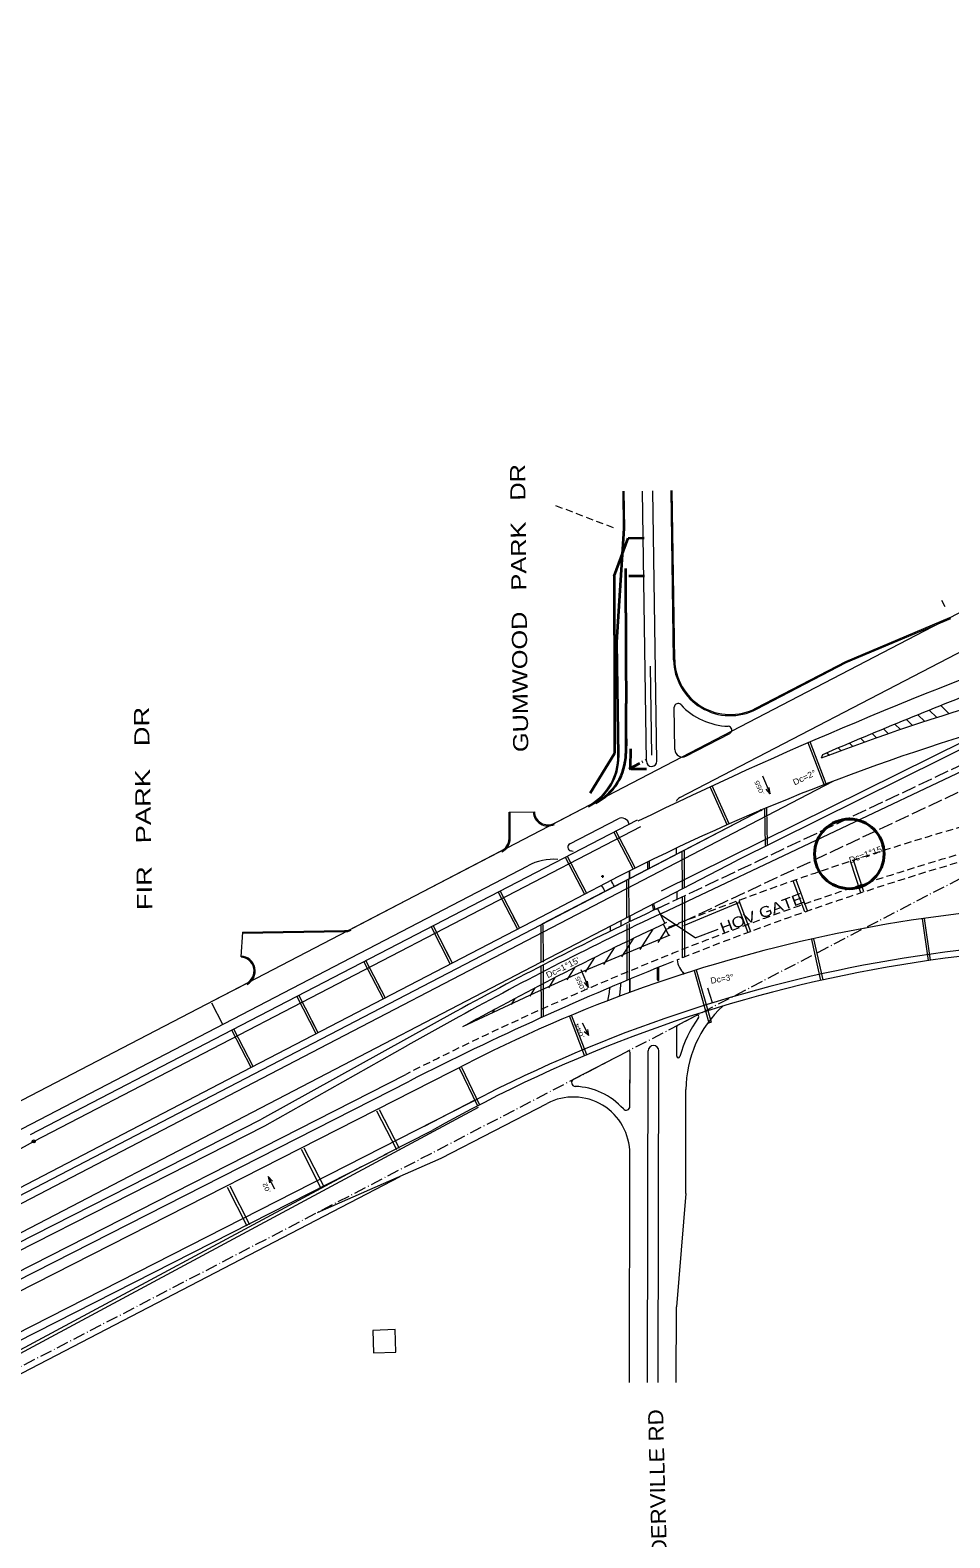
# Model space of a CAD drawing. Extents: x 2354993 to 2372084, y 6966390 to 6990057.
# Drawn here: x 2360871 to 2362087, y 6976825 to 6978818 of the extents above; entities that cross this region are included whole.
import ezdxf
from ezdxf.enums import TextEntityAlignment as Align

# ---------------------------------------------------------------- set-up
doc = ezdxf.new("R2010")
doc.units = 0
doc.header["$LTSCALE"] = 3.2
doc.header["$PDMODE"] = 32
doc.header["$PDSIZE"] = 1.6
for name, pattern in [('DASH_DOUBLE_DOT', [9.2, 5, -1.2, 0.3, -1.2, 0.3, -1.2]), ('DOT_DASHED', [7.7, 5, -1.2, 0.3, -1.2]), ('LONG_DASHED', [7.5, 6, -1.5]), ('MEDIUM_DASHED', [4.5, 3, -1.5])]:
    doc.linetypes.add(name, pattern=pattern)
for name, color, linetype, lineweight in [('1', 7, 'Continuous', 35), ('10', 7, 'Continuous', 13), ('12', 7, 'Continuous', 13), ('13', 7, 'Continuous', 13), ('17', 7, 'Continuous', 13), ('19', 7, 'Continuous', 13), ('22', 7, 'Continuous', 13), ('25', 7, 'Continuous', 13), ('5', 7, 'Continuous', 13), ('6', 7, 'Continuous', 13), ('61', 7, 'Continuous', 13), ('7', 7, 'Continuous', 13), ('8', 7, 'Continuous', 13), ('9', 7, 'Continuous', 13)]:
    doc.layers.add(name, color=color, linetype=linetype, lineweight=lineweight)

msp = doc.modelspace()

# ---------------------------------------------------------------- linework, layer by layer
at = {"layer": '1'}
for p, q in [((2361643.334, 6978096.717), (2361662.094, 6978146.92)), ((2361662.094, 6978146.92), (2361682.893, 6978147.141)), ((2361658.286, 6978106.789), (2361658.569, 6978048.231)), ((2361643.334, 6978096.717), (2361643.569, 6978048.134)), ((2361662.773, 6978096.924), (2361683.427, 6978097.144)), ((2361643.602, 6978048.134), (2361643.989, 6977988.125)), ((2361658.602, 6978048.231), (2361658.989, 6977988.222)), ((2361643.989, 6977988.22), (2361644.052, 6977928.221)), ((2361658.989, 6977988.236), (2361659.052, 6977928.237)), ((2361643.989, 6977928.245), (2361644.009, 6977868.225)), ((2361658.989, 6977928.25), (2361659.009, 6977868.23)), ((2361659.145, 6977881.526), (2361658.901, 6977862.087)), ((2361643.902, 6977862.276), (2361611.578, 6977809.791)), ((2361643.98, 6977868.474), (2361643.902, 6977862.276)), ((2361664.979, 6977868.21), (2361664.662, 6977843.018)), ((2361665.488, 6977841.938), (2361686.142, 6977842.158))]:
    msp.add_line(p, q, dxfattribs=at)
at = {"layer": '1', "lineweight": 40}
msp.add_circle((2361954.426, 6977729.502), 45.991, dxfattribs=at)
at = {"layer": '1'}
msp.add_arc((2361583.907, 6977863.029), 75, 297.46366, 359.28033, dxfattribs=at)
at = {"layer": '10', "linetype": 'DASH_DOUBLE_DOT'}
msp.add_line((2362076.387, 6978064.824), (2362080.803, 6978056.327), dxfattribs=at)
at = {"layer": '10'}
for radius, start, end in [(130, 346.40197, 354.21534), (144, 350.13301, 357.22429)]:
    msp.add_arc((2361508.6, 6977566.022), radius, start, end, dxfattribs=at)
at = {"layer": '12'}
for p, q in [((2361921.078, 6977821.033), (2361899.822, 6977876.283)), ((2361923.878, 6977822.11), (2361902.576, 6977877.48)), ((2361792.739, 6977767.876), (2361770.482, 6977818.12)), ((2361795.484, 6977769.089), (2361773.205, 6977819.384)), ((2361842.059, 6977789.602), (2361842.938, 6977740.473)), ((2361845.031, 6977791.148), (2361845.91, 6977742.017)), ((2361642.915, 6977758.312), (2361668.388, 6977709.168)), ((2361645.58, 6977759.692), (2361671.071, 6977710.513)), ((2361578.716, 6977725.035), (2361604.091, 6977676.078)), ((2361581.379, 6977726.414), (2361606.754, 6977677.459)), ((2361733.026, 6977732.938), (2361733.194, 6977683.439)), ((2361736.019, 6977734.494), (2361736.188, 6977684.995)), ((2361492.591, 6977680.393), (2361518.016, 6977631.341)), ((2361659.537, 6977694.747), (2361659.706, 6977645.247)), ((2361662.531, 6977696.303), (2361662.7, 6977646.803)), ((2361489.928, 6977679.012), (2361515.353, 6977629.96)), ((2361733.232, 6977672.053), (2361733.508, 6977592.186)), ((2361736.227, 6977673.502), (2361736.503, 6977593.373)), ((2361401.146, 6977632.993), (2361426.57, 6977583.943)), ((2361403.809, 6977634.373), (2361429.233, 6977585.323)), ((2361546.229, 6977635.86), (2361546.398, 6977586.361)), ((2361549.229, 6977635.871), (2361549.398, 6977586.371)), ((2361660.108, 6977636.189), (2361660.359, 6977562.375)), ((2361663.102, 6977637.542), (2361663.354, 6977563.627)), ((2361904.379, 6977616.377), (2361916.495, 6977562.288)), ((2361907.22, 6977617.417), (2361919.423, 6977562.942)), ((2361312.364, 6977586.974), (2361337.788, 6977537.924)), ((2361315.027, 6977588.355), (2361340.451, 6977539.305)), ((2361546.412, 6977581.859), (2361546.646, 6977512.847)), ((2361549.412, 6977581.869), (2361549.642, 6977514.202)), ((2361749.245, 6977575.374), (2361768.678, 6977506.355)), ((2361752.054, 6977576.473), (2361771.567, 6977507.169)), ((2361223.582, 6977540.955), (2361249.006, 6977491.906)), ((2361226.245, 6977542.335), (2361251.669, 6977493.286)), ((2361604.345, 6977462.835), (2361584.278, 6977515.485)), ((2361607.115, 6977463.992), (2361587.081, 6977516.552)), ((2361768.678, 6977506.355), (2361771.567, 6977507.169)), ((2361163.464, 6977447.08), (2361137.789, 6977496.485)), ((2361166.127, 6977448.464), (2361140.453, 6977497.866)), ((2361438.43, 6977446.553), (2361462.638, 6977396.418)), ((2361441.294, 6977447.521), (2361465.302, 6977397.803)), ((2361329.187, 6977390.013), (2361355.357, 6977338.869)), ((2361332.748, 6977391.835), (2361358.918, 6977340.691)), ((2361229.481, 6977338.997), (2361255.651, 6977287.852)), ((2361233.042, 6977340.819), (2361259.212, 6977289.674)), ((2361131.556, 6977288.891), (2361157.725, 6977237.746)), ((2361135.117, 6977290.713), (2361161.286, 6977239.568))]:
    msp.add_line(p, q, dxfattribs=at)
at = {"layer": '17'}
for p, q in [((2361706.685, 6977651.285), (2362482.125, 6978018.666)), ((2361735.503, 6977634.987), (2361809.727, 6977665.63)), ((2361715.491, 6977621.611), (2361708.436, 6977636.64)), ((2361438.016, 6977514.121), (2361370.31, 6977476.721)), ((2361610.08, 6977489.34), (2361601.377, 6977505.949)), ((2361610.08, 6977489.34), (2361603.892, 6977494.523)), ((2361610.08, 6977489.34), (2361608.619, 6977497.493)), ((2361185.879, 6977302.985), (2361191.568, 6977296.929))]:
    msp.add_line(p, q, dxfattribs=at)
msp.add_lwpolyline([(2361194.486, 6977286.327), (2361185.879, 6977302.985), (2361187.525, 6977294.842)], dxfattribs=at)
for radius in [4621.662, 4607.662]:
    msp.add_arc((2363672.711, 6973468.642), radius, 115.17558, 118.91596, dxfattribs=at)
at = {"layer": '19'}
for p, q in [((2361849.61, 6977808.832), (2361844.368, 6977815.28)), ((2361609.312, 6977552.985), (2361604.09, 6977559.45))]:
    msp.add_line(p, q, dxfattribs=at)
for points in [[(2361839.453, 6977832.529), (2361849.61, 6977808.832), (2361848.554, 6977817.07)], [(2361599.231, 6977576.714), (2361609.312, 6977552.985), (2361608.283, 6977561.227)]]:
    msp.add_lwpolyline(points, dxfattribs=at)
at = {"layer": '22'}
for p, q in [((2361598.925, 6977692.548), (2361605.381, 6977680.125)), ((2361513.42, 6977640.222), (2361510.193, 6977646.433)), ((2361424.688, 6977594.107), (2361421.46, 6977600.319)), ((2361335.956, 6977547.993), (2361332.727, 6977554.205)), ((2361247.222, 6977501.879), (2361243.995, 6977508.091))]:
    msp.add_line(p, q, dxfattribs=at)
at = {"layer": '25'}
for p, q in [((2358006.591, 6975920.846), (2363488.891, 6978770.331)), ((2361627.907, 6977701.471), (2361627.907, 6977697.971)), ((2361627.907, 6977701.471), (2361627.907, 6977697.971)), ((2361629.657, 6977699.721), (2361626.157, 6977699.721)), ((2361629.657, 6977699.721), (2361626.157, 6977699.721)), ((2361700.849, 6977657.382), (2361710.205, 6977637.472)), ((2361750.672, 6977618.382), (2361704.885, 6977648.793)), ((2361750.672, 6977618.382), (2361781.152, 6977630.088))]:
    msp.add_line(p, q, dxfattribs=at)
at = {"layer": '25', "linetype": 'LONG_DASHED'}
for p, q in [((2361699.088, 6977656.554), (2362455.357, 6978014.169)), ((2361711.836, 6977629.398), (2362366.21, 6977936.92))]:
    msp.add_line(p, q, dxfattribs=at)
at = {"layer": '5'}
for p, q in [((2361655.914, 6978159.454), (2361655.183, 6978208.814)), ((2361657.414, 6978159.476), (2361656.683, 6978208.836)), ((2361685.969, 6977851.923), (2361680.68, 6978209.191)), ((2361699.965, 6977852.247), (2361694.678, 6978209.398)), ((2361721.987, 6977986.095), (2361718.675, 6978209.753)), ((2361723.487, 6977986.117), (2361720.175, 6978209.775)), ((2361646.14, 6978009.412), (2361655.917, 6978159.573)), ((2361647.637, 6978009.315), (2361657.414, 6978159.476)), ((2361730.202, 6977803.996), (2362197.968, 6978047.082)), ((2361949.566, 6977983.686), (2362087.37, 6978041.875)), ((2361950.212, 6977982.331), (2362088.839, 6978040.867)), ((2361648.357, 6977859.309), (2361646.137, 6978009.293)), ((2361649.857, 6977859.331), (2361647.637, 6978009.315)), ((2361830.878, 6977921.989), (2361949.571, 6977983.689)), ((2361831.57, 6977920.658), (2361950.212, 6977982.331)), ((2361723.744, 6977867.403), (2361722.915, 6977923.363)), ((2362075.371, 6977925.53), (2362086.393, 6977914.717)), ((2362183.72, 6977908.026), (2361804.561, 6977720.528)), ((2362014.707, 6977900.992), (2362022.075, 6977893.764)), ((2362029.819, 6977907.181), (2362038.036, 6977899.119)), ((2362044.966, 6977913.333), (2362054.075, 6977904.397)), ((2362060.151, 6977919.449), (2362070.194, 6977909.597)), ((2361738.355, 6977858.679), (2361796.334, 6977888.817)), ((2361969.589, 6977882.216), (2361974.661, 6977877.24)), ((2361984.593, 6977888.51), (2361990.389, 6977882.824)), ((2361999.631, 6977894.769), (2362006.193, 6977888.331)), ((2361918.804, 6977860.536), (2361917.281, 6977856.148)), ((2361924.792, 6977863.122), (2361928.107, 6977859.87)), ((2361939.689, 6977869.522), (2361943.433, 6977865.849)), ((2361954.621, 6977875.887), (2361959.009, 6977871.582)), ((2360066.537, 6976855.596), (2361933.038, 6977825.615)), ((2361504.368, 6977784.529), (2361537.902, 6977785.151)), ((2361504.5, 6977749.834), (2361504.368, 6977784.529)), ((2361506, 6977749.84), (2361505.868, 6977784.535)), ((2361548.215, 6977636.892), (2361839.634, 6977788.342)), ((2361561.261, 6977768.424), (2361612.073, 6977794.834)), ((2361678.27, 6977765.374), (2360875.69, 6977349.365)), ((2361673.771, 6977774.306), (2361137.789, 6977496.485)), ((2361584.83, 6977742.809), (2361648.61, 6977775.962)), ((2361296.77, 6977630.952), (2361494.068, 6977733.5)), ((2361546.398, 6977586.361), (2361804.561, 6977720.528)), ((2361725.789, 6977729.178), (2361725.672, 6977737.124)), ((2360684.022, 6977274.551), (2361529.165, 6977713.873)), ((2361663.702, 6977696.911), (2361663.676, 6977706.798)), ((2361664.258, 6977697.2), (2361664.112, 6977707.018)), ((2361688.076, 6977709.578), (2361687.938, 6977718.887)), ((2361690.062, 6977710.61), (2361689.924, 6977719.864)), ((2361632.519, 6977690.849), (2361546.195, 6977645.987)), ((2361693.524, 6977662.822), (2361695.477, 6977654.856)), ((2361695.297, 6977663.744), (2361697.27, 6977655.699)), ((2361726.672, 6977669.519), (2361726.517, 6977679.969)), ((2361652.731, 6977634.39), (2361652.745, 6977641.63)), ((2361663.857, 6977639.767), (2361663.837, 6977647.394)), ((2361664.743, 6977640.193), (2361664.757, 6977647.873)), ((2361151.723, 6977626.165), (2361149.672, 6977593.441)), ((2361151.723, 6977626.165), (2361286.666, 6977628.28)), ((2361151.746, 6977624.665), (2361286.69, 6977626.78)), ((2361638.718, 6977627.566), (2361638.731, 6977634.346)), ((2361677.647, 6977602.994), (2361694.913, 6977630.236)), ((2361701.411, 6977612.468), (2361711.966, 6977629.121)), ((2361629.721, 6977583.418), (2361643.732, 6977605.524)), ((2361653.751, 6977593.312), (2361669.411, 6977618.02)), ((2358077.838, 6975783.754), (2361546.398, 6977586.361)), ((2361605.553, 6977573.308), (2361617.869, 6977592.739)), ((2361556.793, 6977552.414), (2361565.572, 6977566.265)), ((2361581.245, 6977562.974), (2361591.818, 6977579.656)), ((2361664.111, 6977546.397), (2361664.063, 6977563.923)), ((2361664.559, 6977546.561), (2361664.593, 6977564.144)), ((2361700.592, 6977562.864), (2361700.624, 6977578.98)), ((2361702.591, 6977563.043), (2361702.591, 6977579.779)), ((2361109.814, 6977533.779), (2361157.13, 6977558.372)), ((2361532.191, 6977541.619), (2361539.123, 6977552.556)), ((2361664.558, 6977546.561), (2361664.561, 6977547.827)), ((2361111.023, 6977532.704), (2361125.574, 6977504.248)), ((2361434.148, 6977521.124), (2361176.956, 6977379.053)), ((2361482.528, 6977519.302), (2361485.595, 6977524.142)), ((2361507.437, 6977530.583), (2361512.467, 6977538.519)), ((2361457.462, 6977507.769), (2361458.505, 6977509.414)), ((2361726.393, 6977462.142), (2361726.47, 6977501.354)), ((2361752.443, 6977516.058), (2361727.548, 6977503.125)), ((2361137.789, 6977496.485), (2360871.089, 6977358.243)), ((2361181.489, 6977370.14), (2361370.309, 6977476.721)), ((2361589.813, 6977431.573), (2361661.48, 6977468.803)), ((2361664.262, 6977395.772), (2361664.402, 6977467.025)), ((2361687.545, 6977030.675), (2361688.407, 6977469.268)), ((2361701.545, 6977030.648), (2361702.406, 6977469.37)), ((2360760.653, 6977102.292), (2361453.36, 6977454.625)), ((2361664.264, 6977395.772), (2361664.384, 6977456.789)), ((2360408.239, 6976949.861), (2361368.076, 6977438.13)), ((2360412.773, 6976940.948), (2361372.611, 6977429.217)), ((2360782.414, 6977059.508), (2361475.121, 6977411.841)), ((2361392.655, 6977369.718), (2361458.762, 6977404.061)), ((2361738.037, 6977280.581), (2361738.307, 6977417.899)), ((2361463.639, 6977394.346), (2360737.246, 6977004.45)), ((2361414.784, 6977327.122), (2361554.565, 6977399.738)), ((2360298.445, 6976932.155), (2361176.955, 6977379.053)), ((2360302.979, 6976923.242), (2361181.489, 6977370.14)), ((2361339.374, 6977331.577), (2361402.672, 6977363.773)), ((2360875.69, 6977349.365), (2360349.181, 6977059.2)), ((2360786.947, 6977050.595), (2361343.441, 6977333.646)), ((2361251.074, 6977255.602), (2361414.784, 6977327.122)), ((2361251.074, 6977255.602), (2361414.784, 6977327.122)), ((2361251.074, 6977255.602), (2361414.784, 6977327.122)), ((2361251.074, 6977255.602), (2361414.784, 6977327.122)), ((2361251.074, 6977255.602), (2361414.784, 6977327.122)), ((2361251.074, 6977255.602), (2361414.784, 6977327.122)), ((2361663.546, 6977030.723), (2361664.14, 6977333.036)), ((2361308.647, 6977315.694), (2360735.356, 6977007.975)), ((2361738.037, 6977280.581), (2361725.742, 6977130.598)), ((2361725.546, 6977030.601), (2361725.742, 6977130.598))]:
    msp.add_line(p, q, dxfattribs=at)
at = {"layer": '5', "linetype": 'MEDIUM_DASHED'}
msp.add_line((2361642.446, 6978160.451), (2361564.991, 6978190.191), dxfattribs=at)
at = {"layer": '5'}
for points in [[(2362488.793, 6978067.704), (2362331.734, 6977990.029), (2361705.614, 6977680.376)], [(2360275.595, 6976975.512), (2361546.229, 6977635.86), (2361837.648, 6977787.31)], [(2361546.195, 6977645.986), (2361163.464, 6977447.081), (2360473.907, 6977088.719)], [(2361443.444, 6977501.522), (2361538.676, 6977545.959), (2361596.235, 6977572.076), (2361717.573, 6977622.314)]]:
    msp.add_lwpolyline(points, dxfattribs=at)
msp.add_circle((2360875.69, 6977349.365), 1.982, dxfattribs=at)
for centre, radius, start, end in [((2364188.171, 6972614.757), 5737.613, 103.3303, 115.98006), ((2361796.978, 6977987.205), 75, 180.84795, 297.46641), ((2361796.978, 6977987.205), 73.5, 180.84795, 297.46641), ((2364188.16, 6972614.79), 5715.578, 110.94799, 113.39373), ((2361727.915, 6977923.437), 5, 42.71676, 180.84825), ((2361796.978, 6977987.205), 89, 222.71676, 268.20112), ((2362948.983, 6975157.719), 2888.789, 106.05464, 110.92598), ((2362948.983, 6975157.719), 2854.789, 106.05463, 117.46086), ((2361794.028, 6977893.254), 5, 297.4663, 88.20112), ((2361733.743, 6977867.552), 10, 180.84851, 297.46669), ((2361574.865, 6977858.221), 75, 297.46659, 0.84794), ((2361574.865, 6977858.221), 73.5, 300.40377, 0.84794), ((2361692.966, 6977852.144), 7, 180.85752, 0.84812), ((2361734.814, 6977795.123), 10, 117.46043, 157.69627), ((2361555.777, 6977785.809), 19.387, 182.10935, 296.21641), ((2361555.777, 6977785.809), 17.887, 182.10935, 296.21641), ((2361653.221, 6977767.089), 10, 9.63915, 117.4661), ((2361486.604, 6977749.608), 17.8, 294.63609, 0.64964), ((2361486.604, 6977749.608), 19.3, 294.63609, 0.64964), ((2361587.137, 6977738.373), 5, 117.46586, 255.59834), ((2361563.757, 6977647.327), 75, 86.01267, 117.46634), ((2361563.757, 6977647.327), 89, 73.42744, 75.59834), ((2361563.757, 6977647.327), 75, 25.863, 32.74646), ((2361563.757, 6977647.327), 89, 26.11439, 31.90605), ((2362324.651, 6975741.618), 1921.859, 85.24473, 116.95937), ((2363672.711, 6973468.642), 4629.662, 115.17558, 118.91596), ((2361287.787, 6977644.518), 16.277, 266.05257, 303.50727), ((2361287.826, 6977643.153), 16.413, 266.02968, 298.50649), ((2362324.651, 6975741.618), 1865.859, 81.33444, 119.61246), ((2362324.651, 6975741.618), 1873.859, 81.33444, 116.95937), ((2361148.769, 6977574.72), 18.337, 297.08774, 86.52705), ((2361148.769, 6977574.72), 19.837, 297.08774, 86.52705), ((2363306.843, 6973626.915), 4266, 111.81838, 116.96246), ((2361756.65, 6977592.618), 30, 185.92381, 225.98214), ((2361701.592, 6977563.041), 1, 211.16298, 0.13618), ((2361756.65, 6977592.618), 30, 215.8194, 225.98214), ((2361508.617, 6977576.456), 144, 345.5135, 345.77086), ((2361888.307, 6977417.605), 150, 132.39016, 179.88758), ((2361728.47, 6977501.35), 2, 117.45162, 179.88671), ((2361888.307, 6977417.605), 164, 144.38064, 164.43941), ((2361753.365, 6977514.283), 2, 324.38064, 117.45137), ((2361662.402, 6977467.029), 2, 359.88692, 117.45191), ((2361695.407, 6977469.255), 7, 359.8968, 179.8874), ((2361728.393, 6977462.139), 2, 179.88746, 344.43822), ((2361728.393, 6977462.135), 2, 179.88746, 344.43941), ((2361592.118, 6977427.136), 5, 117.45137, 268.18454), ((2361589.14, 6977333.183), 89, 41.75521, 88.18454), ((2361589.14, 6977333.183), 75, 359.88752, 117.45208), ((2361659.264, 6977395.783), 5, 221.75521, 359.88722)]:
    msp.add_arc(centre, radius, start, end, dxfattribs=at)
at = {"layer": '5', "linetype": 'MEDIUM_DASHED'}
for radius, start, end in [(4310, 96.81172, 111.72863), (4276, 96.81172, 116.96246), (4266, 96.81171, 111.74968)]:
    msp.add_arc((2363306.843, 6973626.915), radius, start, end, dxfattribs=at)
at = {"layer": '6', "linetype": 'DOT_DASHED'}
for p, q in [((2360272.717, 6976747.357), (2363548.144, 6978448.903)), ((2360272.718, 6976747.358), (2363548.137, 6978448.9)), ((2360272.718, 6976747.358), (2363548.137, 6978448.9))]:
    msp.add_line(p, q, dxfattribs=at)
at = {"layer": '6', "linetype": 'DOT_DASHED', "lineweight": 35}
msp.add_line((2361663.017, 6977842.163), (2361685.937, 6977854.076), dxfattribs=at)
at = {"layer": '6'}
msp.add_line((2360276.413, 6976740.261), (2361360.19, 6977303.272), dxfattribs=at)
at = {"layer": '61'}
for p, q in [((2361973.57, 6977679.216), (2361959.818, 6977721.011)), ((2361969.77, 6977677.965), (2361956.019, 6977719.761)), ((2361879.712, 6977694.491), (2361895.008, 6977653.235)), ((2361883.462, 6977695.881), (2361898.759, 6977654.626)), ((2361804.702, 6977666.679), (2361819.999, 6977625.423)), ((2361808.452, 6977668.069), (2361823.749, 6977626.814)), ((2362058.98, 6977588.466), (2362051.006, 6977643.896)), ((2362061.949, 6977588.891), (2362053.976, 6977644.321)), ((2361773.414, 6977532.563), (2361767.454, 6977551.926))]:
    msp.add_line(p, q, dxfattribs=at)
at = {"layer": '7'}
msp.add_lwpolyline([(2361324.066, 6977099.727), (2361324.976, 6977070.174), (2361354.789, 6977071.097), (2361353.879, 6977100.639)], close=True, dxfattribs=at)
at = {"layer": '8'}
msp.add_line((2361691.11, 6977977.442), (2361692.85, 6977859.968), dxfattribs=at)
at = {"layer": '9'}
msp.add_arc((2360722.521, 6984327.136), 5729.573, 359.50797, 359.50797, dxfattribs=at)
msp.add_point((2361837.653, 6977787.312), dxfattribs=at)

# ---------------------------------------------------------------- texts
at = {"layer": '13'}
for s, rotation, width, p in [('GUMWOOD   PARK   DR', 90.634, 1.25, (2361527.72, 6978054.545)), ('FIR   PARK   DR', 90.937, 1.35, (2361030.284, 6977789.731))]:
    msp.add_text(s, height=20, rotation=rotation, dxfattribs=dict(at, width=width)).set_placement(p, align=Align.CENTER)
at = {"layer": '13', "width": 1.1}
msp.add_text('HANDLEY-EDERVILLE RD', height=20, rotation=91.516, dxfattribs=at).set_placement((2361717.559, 6976634.442))
at = {"layer": '17'}
for s, height, rotation, width, p in [('Dc=2°', 8, 25.472, 1.1, (2361882.048, 6977819.9)), ("Dc=1°15'", 8, 20.149, 1.1, (2361955.69, 6977717.017)), ("Dc=1°15'", 8, 26.282, 1.1, (2361555.616, 6977565.08)), ('Dc=3°', 8, 10.149, 1.05, (2361771.529, 6977557.786)), ('.044', 6, 114.81, 1.35, (2361604.498, 6977487.127)), ('.02', 6, 114.478, 1.3, (2361189.315, 6977282.55))]:
    msp.add_text(s, height=height, rotation=rotation, dxfattribs=dict(at, width=width)).set_placement(p)
at = {"layer": '19', "width": 1.3}
for height, rotation, p in [(5.999, 114.154, (2361842.344, 6977808.858)), (6, 114.079, (2361605.426, 6977549.938))]:
    msp.add_text('.055', height=height, rotation=rotation, dxfattribs=at).set_placement(p)
at = {"layer": '25', "width": 1.2}
msp.add_text('HOV GATE', height=14, rotation=20.62, dxfattribs=at).set_placement((2361786.588, 6977624.386))

doc.saveas('drawing.dxf')
